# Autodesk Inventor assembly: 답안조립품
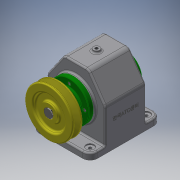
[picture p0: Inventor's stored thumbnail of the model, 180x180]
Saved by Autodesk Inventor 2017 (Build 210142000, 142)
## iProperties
Part Number: 답안조립품
Material: 일반
Document SubType Name: Assembly
Designer: MRC
Author: MRC
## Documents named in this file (15)
- C:\Users\MRC\Desktop\721206V1007\답안조립품.iam
- C:\Users\MRC\Desktop\721206V1007\본체.ipt
- C:\Users\MRC\Desktop\721206V1007\축.ipt
- C:\Users\MRC\Desktop\721206V1007\앞커버.ipt
- C:\Users\MRC\Desktop\721206V1007\뒤커버.ipt
- C:\Users\MRC\Desktop\721206V1007\키 - 6 x 6 x 22.ipt
- C:\Users\MRC\Desktop\721206V1007\스퍼기어.ipt
- C:\Users\MRC\Desktop\721206V1007\칼라.ipt
- C:\Users\MRC\Desktop\721206V1007\베어링 6203.ipt
- C:\Users\MRC\Desktop\721206V1007\오일 실 17 x 32 x 8.ipt
- C:\Users\MRC\Desktop\721206V1007\볼트 M3 x 8.ipt
- C:\Users\MRC\Desktop\721206V1007\볼트 M3 x 10.ipt
- C:\Users\MRC\Desktop\721206V1007\키 - 5 x 5 x 18.ipt
- C:\Users\MRC\Desktop\721206V1007\V-벨트풀리.ipt
- C:\Users\MRC\Desktop\721206V1007\멈춤나사 - M4x10.ipt
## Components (9 placed, 3 different names)
1. ISO 4762 M3 x 8:1
2. ISO 4762 M3 x 8:2
3. ISO 4762 M3 x 8:3
4. ISO 4762 M3 x 8:4
5. ISO 4762 M3 x 10:1
6. ISO 4762 M3 x 10:2
7. ISO 4762 M3 x 10:3
8. ISO 4762 M3 x 10:4
9. V-벨트풀리:1
